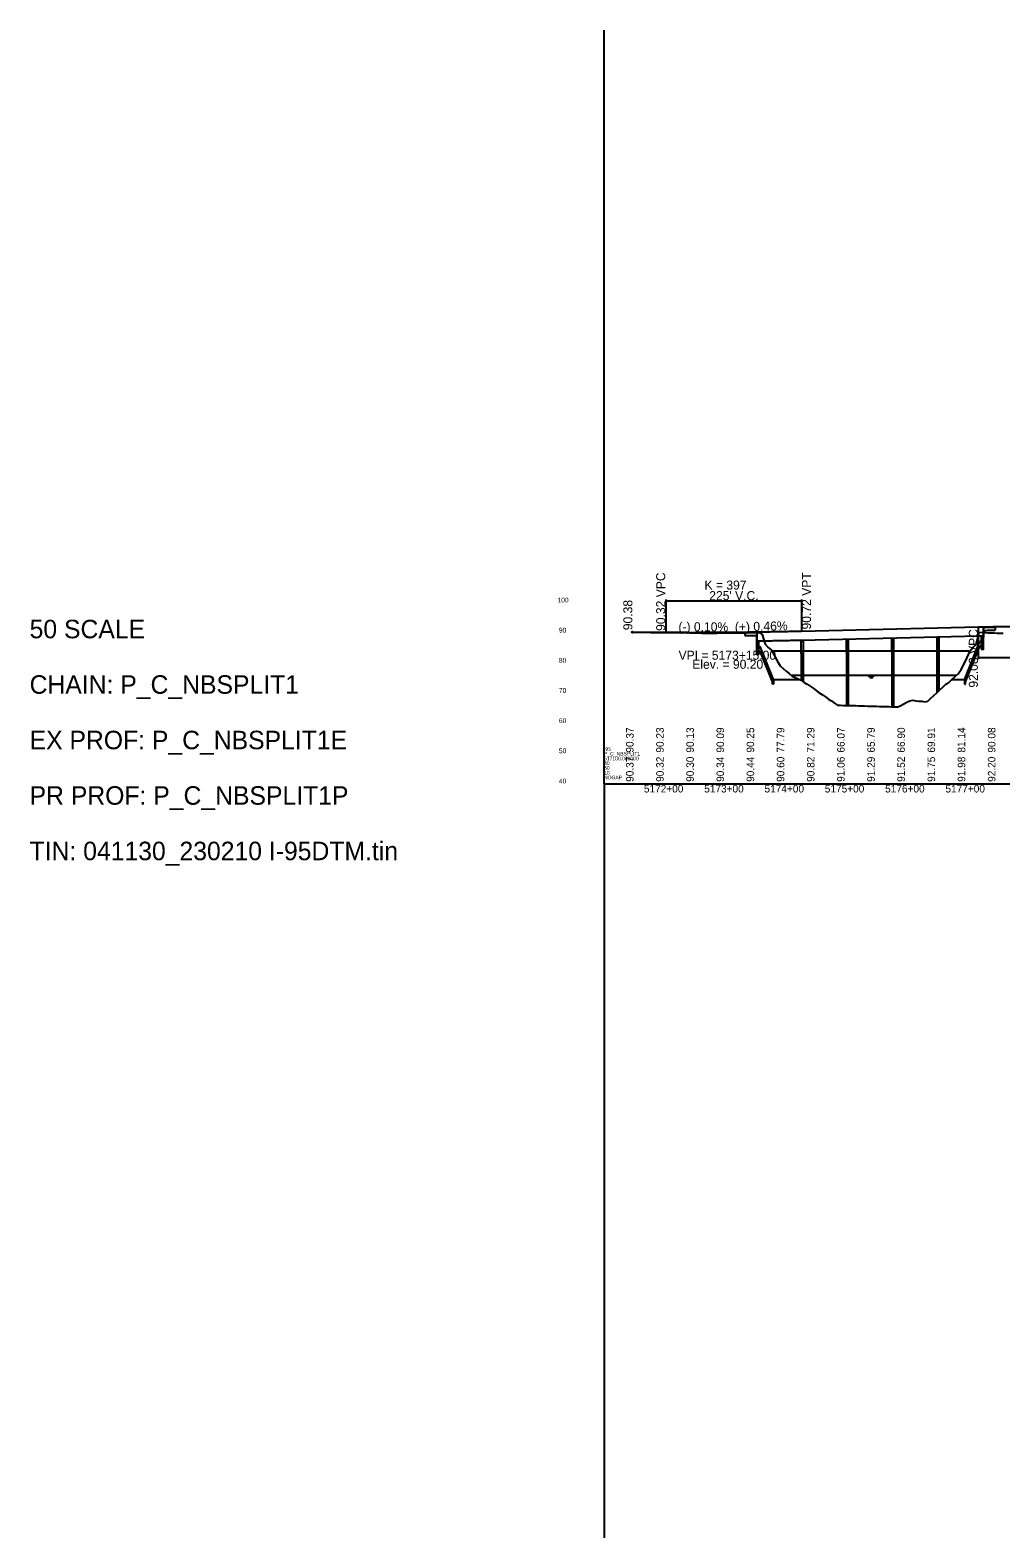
# Model space of a CAD drawing. Extents: x 2121671 to 2169879, y 557274 to 599957.
# Drawn here: x 2145717 to 2147326, y 597457 to 599957 of the extents above; entities that cross this region are included whole.
import ezdxf

# ---------------------------------------------------------------- set-up
doc = ezdxf.new("R2010")
doc.units = 0
for name, color, linetype in [('BR_CONCRETE', 7, 'Continuous'), ('BR_DETAILS', 7, 'Continuous'), ('BR_PRESTRESSED BEAM', 7, 'Continuous'), ('RD_DDB_ElevTX', 7, 'Continuous'), ('RD_DDB_GradeTX', 7, 'Continuous'), ('RD_DDB_Profile_Elev', 7, 'Continuous'), ('RD_DDB_Profile_EX', 7, 'Continuous'), ('RD_DDB_Profile_Lbl', 7, 'Continuous'), ('RD_DDB_Profile_PR', 7, 'Continuous'), ('RD_DDB_StaTX', 7, 'Continuous'), ('RD_DDB_StripGrade', 7, 'Continuous'), ('RD_DDB_VCLbl', 7, 'Continuous'), ('RD_GPK_Profile_Cell', 7, 'Continuous'), ('RD_HC_Data_Rel', 7, 'Continuous')]:
    doc.layers.add(name, color=color, linetype=linetype)

msp = doc.modelspace()

# ---------------------------------------------------------------- linework, layer by layer
at = {"layer": 'BR_CONCRETE'}
for p, q in [((2146901.8, 598958.6), (2146901.8, 598953.6)), ((2146901.8, 598958.6), (2146901.8, 598953.6)), ((2146921.1, 598953.9), (2146921.1, 598942.7)), ((2146921.1, 598953.9), (2146921.1, 598942.7)), ((2146921.8, 598959.7), (2146921.8, 598942.7)), ((2146921.8, 598959.7), (2146921.8, 598942.7)), ((2146995.7, 598961.1), (2147289.1, 598967.9)), ((2146995.7, 598961.1), (2147289.1, 598967.9)), ((2147289.1, 598967.9), (2147296.8, 598968)), ((2147289.1, 598967.9), (2147296.8, 598968)), ((2147296.8, 598968), (2147296.8, 598951)), ((2147296.8, 598968), (2147296.8, 598951)), ((2147297.5, 598962.2), (2147297.5, 598951)), ((2147297.5, 598962.2), (2147297.5, 598951)), ((2147316.8, 598967.6), (2147316.8, 598962.6)), ((2147316.8, 598967.6), (2147316.8, 598962.6)), ((2147070.3, 598925.8), (2147070.3, 598837.8)), ((2147070.3, 598925.8), (2147070.3, 598837.8)), ((2147073.3, 598925.8), (2147073.3, 598837.7)), ((2147073.3, 598925.8), (2147073.3, 598837.7)), ((2147145.3, 598927.6), (2147145.3, 598835.6)), ((2147145.3, 598927.6), (2147145.3, 598835.6)), ((2147148.3, 598927.6), (2147148.3, 598835.6)), ((2147148.3, 598927.6), (2147148.3, 598835.6)), ((2147220.3, 598929.3), (2147220.3, 598858.9)), ((2147220.3, 598929.3), (2147220.3, 598858.9)), ((2147223.3, 598929.3), (2147223.3, 598861.7)), ((2147223.3, 598929.3), (2147223.3, 598861.7)), ((2146995.3, 598924.1), (2146995.3, 598879.3)), ((2146995.3, 598924.1), (2146995.3, 598879.3)), ((2146998.3, 598924.1), (2146998.3, 598877.2)), ((2146998.3, 598924.1), (2146998.3, 598877.2))]:
    msp.add_line(p, q, dxfattribs=at)
for points in [[(2147293.5, 598931), (2147297.5, 598931), (2147297.5, 598951), (2147293.5, 598951)], [(2147293.5, 598931), (2147297.5, 598931), (2147297.5, 598951), (2147293.5, 598951)], [(2146921.1, 598922.7), (2146925.1, 598922.7), (2146925.1, 598942.7), (2146921.1, 598942.7)], [(2146921.1, 598922.7), (2146925.1, 598922.7), (2146925.1, 598942.7), (2146921.1, 598942.7)], [(2146994.8, 598924.1), (2146998.8, 598924.1), (2146998.8, 598944.1), (2146994.8, 598944.1)], [(2146994.8, 598924.1), (2146998.8, 598924.1), (2146998.8, 598944.1), (2146994.8, 598944.1)], [(2147069.8, 598925.8), (2147073.8, 598925.8), (2147073.8, 598945.8), (2147069.8, 598945.8)], [(2147069.8, 598925.8), (2147073.8, 598925.8), (2147073.8, 598945.8), (2147069.8, 598945.8)], [(2147144.8, 598927.6), (2147148.8, 598927.6), (2147148.8, 598947.6), (2147144.8, 598947.6)], [(2147144.8, 598927.6), (2147148.8, 598927.6), (2147148.8, 598947.6), (2147144.8, 598947.6)], [(2147219.8, 598929.3), (2147223.8, 598929.3), (2147223.8, 598949.3), (2147219.8, 598949.3)], [(2147219.8, 598929.3), (2147223.8, 598929.3), (2147223.8, 598949.3), (2147219.8, 598949.3)]]:
    msp.add_lwpolyline(points, close=True, dxfattribs=at)
for points in [[(2146901.8, 598958.6), (2146905.6, 598958.7), (2146910.1, 598958.7), (2146914.6, 598958.8), (2146919.1, 598958.8), (2146921.8, 598958.9)], [(2146901.8, 598958.6), (2146905.6, 598958.7), (2146910.1, 598958.7), (2146914.6, 598958.8), (2146919.1, 598958.8), (2146921.8, 598958.9)], [(2146901.8, 598953.6), (2146905.6, 598953.7), (2146910.1, 598953.7), (2146914.6, 598953.8), (2146919.1, 598953.8), (2146921.8, 598953.9)], [(2146901.8, 598953.6), (2146905.6, 598953.7), (2146910.1, 598953.7), (2146914.6, 598953.8), (2146919.1, 598953.8), (2146921.8, 598953.9)], [(2146921.8, 598959.7), (2146923.7, 598959.7), (2146928.2, 598959.8), (2146932.7, 598959.9), (2146937.2, 598959.9), (2146941.7, 598960), (2146946.2, 598960.1), (2146950.7, 598960.2), (2146955.2, 598960.2), (2146959.7, 598960.3), (2146964.2, 598960.4), (2146968.7, 598960.5), (2146973.2, 598960.6), (2146977.7, 598960.7), (2146982.2, 598960.8), (2146986.7, 598960.9), (2146991.2, 598961), (2146995.7, 598961.1)], [(2146921.8, 598959.7), (2146923.7, 598959.7), (2146928.2, 598959.8), (2146932.7, 598959.9), (2146937.2, 598959.9), (2146941.7, 598960), (2146946.2, 598960.1), (2146950.7, 598960.2), (2146955.2, 598960.2), (2146959.7, 598960.3), (2146964.2, 598960.4), (2146968.7, 598960.5), (2146973.2, 598960.6), (2146977.7, 598960.7), (2146982.2, 598960.8), (2146986.7, 598960.9), (2146991.2, 598961), (2146995.7, 598961.1)], [(2147296.8, 598967.2), (2147298.1, 598967.2), (2147307.1, 598967.4), (2147316.1, 598967.6), (2147316.8, 598967.6)], [(2147296.8, 598967.2), (2147298.1, 598967.2), (2147307.1, 598967.4), (2147316.1, 598967.6), (2147316.8, 598967.6)], [(2147296.8, 598962.2), (2147298.1, 598962.2), (2147307.1, 598962.4), (2147316.1, 598962.6), (2147316.8, 598962.6)], [(2147296.8, 598962.2), (2147298.1, 598962.2), (2147307.1, 598962.4), (2147316.1, 598962.6), (2147316.8, 598962.6)]]:
    msp.add_spline(points, degree=3, dxfattribs=at)
at = {"layer": 'BR_DETAILS'}
for p, q in [((2146925.1, 598935.2), (2146927.1, 598935.2)), ((2146925.1, 598935.2), (2146927.1, 598935.2)), ((2146925.1, 598927.7), (2146927.1, 598927.7)), ((2146925.1, 598927.7), (2146927.1, 598927.7)), ((2146949, 598880.5), (2146927.1, 598935.2)), ((2146949, 598880.5), (2146927.1, 598935.2)), ((2146947.5, 598876.7), (2146927.1, 598927.7)), ((2146947.5, 598876.7), (2146927.1, 598927.7)), ((2147266.2, 598880.4), (2147291.5, 598943.5)), ((2147266.2, 598880.4), (2147291.5, 598943.5)), ((2147267.7, 598876.7), (2147291.5, 598936)), ((2147267.7, 598876.7), (2147291.5, 598936)), ((2147293.5, 598943.5), (2147291.5, 598943.5)), ((2147293.5, 598943.5), (2147291.5, 598943.5)), ((2147293.5, 598936), (2147291.5, 598936)), ((2147293.5, 598936), (2147291.5, 598936)), ((2146947.5, 598873), (2146947.5, 598876.7)), ((2146947.5, 598873), (2146947.5, 598876.7)), ((2146949, 598880.5), (2146993, 598880.5)), ((2146949, 598880.5), (2146949, 598873)), ((2146949, 598880.5), (2146993, 598880.5)), ((2146949, 598880.5), (2146949, 598873)), ((2147266.2, 598880.4), (2147244.7, 598880.4)), ((2147266.2, 598880.4), (2147244.7, 598880.4)), ((2147266.2, 598880.4), (2147266.2, 598872.9)), ((2147266.2, 598880.4), (2147266.2, 598872.9)), ((2147267.7, 598872.9), (2147267.7, 598876.7)), ((2147267.7, 598872.9), (2147267.7, 598876.7)), ((2146949, 598873), (2146947.5, 598873)), ((2146949, 598873), (2146947.5, 598873)), ((2147266.2, 598872.9), (2147267.7, 598872.9)), ((2147266.2, 598872.9), (2147267.7, 598872.9))]:
    msp.add_line(p, q, dxfattribs=at)
at = {"layer": 'BR_PRESTRESSED BEAM'}
for p, q in [((2146995.7, 598946.1), (2147289.1, 598952.9)), ((2146995.7, 598946.1), (2147289.1, 598952.9)), ((2147289.1, 598952.9), (2147296.8, 598953)), ((2147289.1, 598952.9), (2147296.8, 598953))]:
    msp.add_line(p, q, dxfattribs=at)
msp.add_spline([(2146921.8, 598944.7), (2146923.7, 598944.7), (2146928.2, 598944.8), (2146932.7, 598944.9), (2146937.2, 598944.9), (2146941.7, 598945), (2146946.2, 598945.1), (2146950.7, 598945.2), (2146955.2, 598945.2), (2146959.7, 598945.3), (2146964.2, 598945.4), (2146968.7, 598945.5), (2146973.2, 598945.6), (2146977.7, 598945.7), (2146982.2, 598945.8), (2146986.7, 598945.9), (2146991.2, 598946), (2146995.7, 598946.1)], degree=3, dxfattribs=at)
msp.add_spline([(2146921.8, 598944.7), (2146923.7, 598944.7), (2146928.2, 598944.8), (2146932.7, 598944.9), (2146937.2, 598944.9), (2146941.7, 598945), (2146946.2, 598945.1), (2146950.7, 598945.2), (2146955.2, 598945.2), (2146959.7, 598945.3), (2146964.2, 598945.4), (2146968.7, 598945.5), (2146973.2, 598945.6), (2146977.7, 598945.7), (2146982.2, 598945.8), (2146986.7, 598945.9), (2146991.2, 598946), (2146995.7, 598946.1)], degree=3, dxfattribs=at)
at = {"layer": 'RD_DDB_GradeTX'}
for p, q in [((2146821.2, 598958.8), (2146882.2, 598958.5)), ((2146945.2, 598959.9), (2146884.2, 598958.5))]:
    msp.add_line(p, q, dxfattribs=at)
for centre in [(2146715.2, 598959.3), (2146883.2, 598958.5)]:
    msp.add_circle(centre, 1, dxfattribs=at)
at = {"layer": 'RD_DDB_Profile_Elev'}
for p, q in [((2146946.4, 598928.1), (2147275.2, 598928.1)), ((2146978.1, 598888.1), (2147252.9, 598888.1)), ((2147106.2, 598886.8), (2147116.2, 598886.8)), ((2147107.5, 598885.6), (2147115, 598885.6)), ((2147108.7, 598884.3), (2147113.7, 598884.3))]:
    msp.add_line(p, q, dxfattribs=at)
at = {"layer": 'RD_DDB_Profile_EX'}
for points in [[(2146715.2, 598959.3), (2146720.2, 598959.3), (2146725.2, 598959.2), (2146730.2, 598959.1), (2146735.2, 598959.1), (2146740.2, 598959), (2146745.2, 598958.9), (2146750.2, 598958.8), (2146755.2, 598958.7), (2146760.2, 598958.6), (2146765.2, 598958.6), (2146770.2, 598958.6), (2146775.2, 598958.6), (2146780.2, 598958.6), (2146785.2, 598958.7), (2146790.2, 598958.7), (2146795.2, 598958.7), (2146800.2, 598958.7), (2146805.2, 598958.5), (2146810.2, 598958.4), (2146815.2, 598958.2), (2146820.2, 598958.1), (2146825.2, 598957.9), (2146830.2, 598957.8), (2146835.2, 598957.8), (2146840.2, 598957.8), (2146845.2, 598957.8), (2146850.2, 598957.8), (2146855.2, 598957.8), (2146860.2, 598957.9), (2146865.2, 598957.9), (2146870.2, 598957.9), (2146875.2, 598958), (2146880.2, 598958), (2146885.2, 598958.1), (2146890.2, 598958.2), (2146895.2, 598958.3), (2146900.2, 598958.4), (2146905.2, 598958.5), (2146910.2, 598958.6), (2146915.2, 598958.7), (2146920.2, 598958.8), (2146925.2, 598958.8), (2146930.2, 598955.1), (2146935.2, 598939.3), (2146940.2, 598933.8), (2146945.2, 598930.2), (2146950.2, 598920.9), (2146955.2, 598911.6), (2146960.2, 598903.3), (2146965.2, 598898.9), (2146970.2, 598894.7), (2146975.2, 598890.6), (2146980.2, 598886.2), (2146985.2, 598884.3), (2146990.2, 598881.9), (2146995.2, 598879.4), (2147000.2, 598875.8), (2147005.2, 598873.2), (2147010.2, 598869.8), (2147015.2, 598866.3), (2147020.2, 598862.4), (2147025.2, 598858.8), (2147030.2, 598855.2), (2147035.2, 598851.8), (2147040.2, 598848.4), (2147045.2, 598845.1), (2147050.2, 598841.7), (2147055.2, 598838.3), (2147060.2, 598838.1), (2147065.2, 598837.9), (2147070.2, 598837.8), (2147075.2, 598837.6), (2147080.2, 598837.5), (2147085.2, 598837.4), (2147090.2, 598837.2), (2147095.2, 598837.1), (2147100.2, 598836.9), (2147105.2, 598836.8), (2147110.2, 598836.6), (2147115.2, 598836.5), (2147120.2, 598836.4), (2147125.2, 598836.2), (2147130.2, 598836.1), (2147135.2, 598835.9), (2147140.2, 598835.8), (2147145.2, 598835.6), (2147150.2, 598835.5), (2147155.2, 598835.4), (2147160.2, 598837.9), (2147165.2, 598840.4), (2147170.2, 598843), (2147175.2, 598845.6), (2147180.2, 598846.4), (2147185.2, 598845.3), (2147190.2, 598844.7), (2147195.2, 598844.8), (2147200.2, 598843.7), (2147205.2, 598845), (2147210.2, 598849.6), (2147215.2, 598854.2)], [(2147215.2, 598854.2), (2147220.2, 598858.9), (2147225.2, 598863.5), (2147230.2, 598868.2), (2147235.2, 598872.8), (2147240.2, 598876), (2147245.2, 598881), (2147250.2, 598885.6), (2147255.2, 598890.3), (2147260.2, 598897.2), (2147265.2, 598906.8), (2147270.2, 598917.4), (2147275.2, 598928.2), (2147280.2, 598934.1), (2147285.2, 598938.7), (2147290.2, 598959), (2147295.2, 598958.8), (2147300.2, 598958.6), (2147305.2, 598958.4), (2147310.2, 598958.2), (2147315.2, 598958), (2147320.2, 598957.8), (2147325.2, 598957.6), (2147330.2, 598957.4)]]:
    msp.add_lwpolyline(points, dxfattribs=at)
at = {"layer": 'RD_DDB_Profile_PR'}
for p, q in [((2146715.2, 598959.3), (2146770.7, 598959.1)), ((2146995.7, 598961.1), (2147289.1, 598967.9))]:
    msp.add_line(p, q, dxfattribs=at)
for points in [[(2146770.7, 598959.1), (2146775.2, 598959), (2146779.7, 598959), (2146784.2, 598959), (2146788.7, 598959), (2146793.2, 598959), (2146797.7, 598959), (2146802.2, 598959), (2146806.7, 598959), (2146811.2, 598958.9), (2146815.7, 598958.9), (2146820.2, 598959), (2146824.7, 598959), (2146829.2, 598959), (2146833.7, 598959), (2146838.2, 598959), (2146842.7, 598959), (2146847.2, 598959), (2146851.7, 598959), (2146856.2, 598959.1), (2146860.7, 598959.1), (2146865.2, 598959.1), (2146869.7, 598959.2), (2146874.2, 598959.2), (2146878.7, 598959.2), (2146883.2, 598959.3), (2146887.7, 598959.3), (2146892.2, 598959.4), (2146896.7, 598959.4), (2146901.2, 598959.4), (2146905.7, 598959.5), (2146910.2, 598959.6), (2146914.7, 598959.6), (2146919.2, 598959.7), (2146923.7, 598959.7), (2146928.2, 598959.8), (2146932.7, 598959.9), (2146937.2, 598959.9), (2146941.7, 598960), (2146946.2, 598960.1), (2146950.7, 598960.2), (2146955.2, 598960.2), (2146959.7, 598960.3), (2146964.2, 598960.4), (2146968.7, 598960.5), (2146973.2, 598960.6), (2146977.7, 598960.7), (2146982.2, 598960.8), (2146986.7, 598960.9), (2146991.2, 598961), (2146995.7, 598961.1)], [(2147289.1, 598967.9), (2147298.1, 598968.1), (2147307.1, 598968.3), (2147316.1, 598968.4), (2147325.1, 598968.6), (2147334.1, 598968.8), (2147343.1, 598968.9), (2147352.1, 598969.1), (2147361.1, 598969.2), (2147370.1, 598969.4), (2147379.1, 598969.5), (2147388.1, 598969.6), (2147397.1, 598969.7), (2147406.1, 598969.8), (2147415.1, 598969.9), (2147424.1, 598970), (2147433.1, 598970), (2147442.1, 598970.1), (2147451.1, 598970.2), (2147460.1, 598970.2), (2147469.1, 598970.2), (2147478.1, 598970.3), (2147487.1, 598970.3), (2147496.1, 598970.3), (2147505.1, 598970.3), (2147514.1, 598970.3), (2147523.1, 598970.2), (2147532.1, 598970.2), (2147541.1, 598970.2), (2147550.1, 598970.1), (2147559.1, 598970.1), (2147568.1, 598970), (2147577.1, 598969.9), (2147586.1, 598969.8), (2147595.1, 598969.7), (2147604.1, 598969.6), (2147613.1, 598969.5), (2147622.1, 598969.4), (2147631.1, 598969.3), (2147640.1, 598969.1), (2147649.1, 598969), (2147658.1, 598968.8), (2147667.1, 598968.7), (2147676.1, 598968.5), (2147685.1, 598968.3), (2147694.1, 598968.1), (2147703.1, 598967.9), (2147712.1, 598967.7), (2147721.1, 598967.5), (2147730.1, 598967.3), (2147739.1, 598967)]]:
    msp.add_spline(points, degree=3, dxfattribs=at)
at = {"layer": 'RD_DDB_VCLbl'}
for p, q in [((2146770.7, 599013.6), (2146770.7, 598959.1)), ((2146770.7, 599011.1), (2146995.7, 599011.1)), ((2146995.7, 599013.6), (2146995.7, 598961.1)), ((2147289.1, 598914.5), (2147289.1, 598967.9)), ((2147289.1, 598917), (2147739.1, 598917))]:
    msp.add_line(p, q, dxfattribs=at)
at = {"layer": 'RD_GPK_Profile_Cell'}
for q in [(2146668.2, 599957.5), (2146668.2, 599957.5), (2146668.2, 599957.5), (2151268.2, 598707.5), (2146668.2, 597457.5), (2151268.2, 598707.5), (2146668.2, 597457.5), (2151268.2, 598707.5), (2146668.2, 597457.5)]:
    msp.add_line((2146668.2, 598707.5), q, dxfattribs=at)

# ---------------------------------------------------------------- texts
at = {"layer": 'RD_DDB_ElevTX'}
for s, p in [('100', (2146591, 599008.5)), ('90', (2146593.4, 598958.5)), ('80', (2146593.4, 598908.5)), ('70', (2146593.4, 598858.5)), ('60', (2146593.4, 598808.5)), ('50', (2146593.4, 598758.5)), ('40', (2146593.4, 598708.5))]:
    msp.add_text(s, height=8, dxfattribs=at).set_placement(p)
at = {"layer": 'RD_DDB_GradeTX'}
for s, rotation, p in [('(-) 0.10%', 359.7004, (2146791.6, 598960.9)), ('(+) 0.46%', 1.3258, (2146885.3, 598960.5))]:
    msp.add_text(s, height=15, rotation=rotation, dxfattribs=at).set_placement(p)
at = {"layer": 'RD_DDB_Profile_Lbl'}
msp.add_text('90.38', height=15, rotation=90, dxfattribs=at).set_placement((2146715.2, 598962.5))
for s, p in [('VPI = 5173+15.00', (2146791.8, 598913.5)), ('Elev. = 90.20', (2146814.5, 598898.5))]:
    msp.add_text(s, height=15, dxfattribs=at).set_placement(p)
at = {"layer": 'RD_DDB_StaTX'}
for s, p in [('5172+00', (2146734.3, 598693.4)), ('5173+00', (2146834.3, 598693.4)), ('5174+00', (2146934.3, 598693.4)), ('5175+00', (2147034.3, 598693.4)), ('5176+00', (2147134.3, 598693.4)), ('5177+00', (2147234.3, 598693.4))]:
    msp.add_text(s, height=12.5, dxfattribs=at).set_placement(p)
at = {"layer": 'RD_DDB_StripGrade'}
for s, height, p in [('90.32 VPC', 15, (2146769.7, 598961.3)), ('90.72 VPT', 15, (2147011.4, 598963.7)), ('92.08 VPC', 15, (2147288.1, 598867.3)), ('90.37', 12.5, (2146717.2, 598759.5)), ('90.23', 12.5, (2146767.2, 598759.5)), ('90.13', 12.5, (2146817.2, 598759.5)), ('90.09', 12.5, (2146867.2, 598759.5)), ('90.25', 12.5, (2146917.2, 598759.5)), ('77.79', 12.5, (2146967.2, 598759.5)), ('71.29', 12.5, (2147017.2, 598759.5)), ('66.07', 12.5, (2147067.2, 598759.5)), ('65.79', 12.5, (2147117.2, 598759.5)), ('66.90', 12.5, (2147167.2, 598759.5)), ('69.91', 12.5, (2147217.2, 598759.5)), ('81.14', 12.5, (2147267.2, 598759.5)), ('90.08', 12.5, (2147317.2, 598759.5)), ('90.37', 12.5, (2146717.2, 598711)), ('90.32', 12.5, (2146767.2, 598711)), ('90.30', 12.5, (2146817.2, 598711)), ('90.34', 12.5, (2146867.2, 598711)), ('90.44', 12.5, (2146917.2, 598711)), ('90.60', 12.5, (2146967.2, 598711)), ('90.82', 12.5, (2147017.2, 598711)), ('91.06', 12.5, (2147067.2, 598711)), ('91.29', 12.5, (2147117.2, 598711)), ('91.52', 12.5, (2147167.2, 598711)), ('91.75', 12.5, (2147217.2, 598711)), ('91.98', 12.5, (2147267.2, 598711)), ('92.20', 12.5, (2147317.2, 598711))]:
    msp.add_text(s, height=height, rotation=90, dxfattribs=at).set_placement(p)
at = {"layer": 'RD_DDB_VCLbl'}
for s, p in [('K = 397', (2146834.8, 599029.8)), ("225' V.C.", (2146842.7, 599012.3))]:
    msp.add_text(s, height=15, dxfattribs=at).set_placement(p)
at = {"layer": 'RD_GPK_Profile_Cell'}
for s, height, p in [('517100.000000', 6, (2146668.2, 598746.8)), ('517100.000000', 6, (2146668.2, 598746.8)), ('P_C_NBSPLIT1', 6, (2146668.2, 598754.7)), ('P_C_NBSPLIT1', 6, (2146668.2, 598754.7)), ('I95', 6, (2146668.2, 598762.5)), ('I95', 6, (2146668.2, 598762.5)), ('40', 6, (2146668.2, 598738.9)), ('40', 6, (2146668.2, 598738.9)), ('50', 6, (2146668.2, 598731.1)), ('50', 6, (2146668.2, 598731.1)), ('10', 6, (2146668.2, 598723.2)), ('10', 6, (2146668.2, 598723.2)), ('I95', 0.208, (2146668.2, 598711.8)), ('P_C_NBSPLIT1', 0.208, (2146668.2, 598711.2)), ('517100.000000', 0.208, (2146668.2, 598710.6)), ('40', 0.208, (2146668.2, 598710)), ('50', 0.208, (2146668.2, 598709.3)), ('10', 0.208, (2146668.2, 598708.7)), ('NOGAP', 0.208, (2146668.2, 598708.1)), ('NOGAP', 6, (2146668.2, 598715.3)), ('NOGAP', 6, (2146668.2, 598715.3))]:
    msp.add_text(s, height=height, dxfattribs=at).set_placement(p)
at = {"layer": 'RD_HC_Data_Rel'}
for s, height, p in [('50 SCALE', 30.67, (2145715.7, 598949.1)), ('CHAIN: P_C_NBSPLIT1', 30.668, (2145715.7, 598857.1)), ('EX PROF: P_C_NBSPLIT1E', 30.668, (2145715.7, 598765.1)), ('PR PROF: P_C_NBSPLIT1P', 30.668, (2145715.7, 598673.1)), ('TIN: 041130_230210 I-95DTM.tin', 30.668, (2145715.7, 598581.1))]:
    msp.add_text(s, height=height, rotation=360, dxfattribs=at).set_placement(p)

doc.saveas('drawing.dxf')
